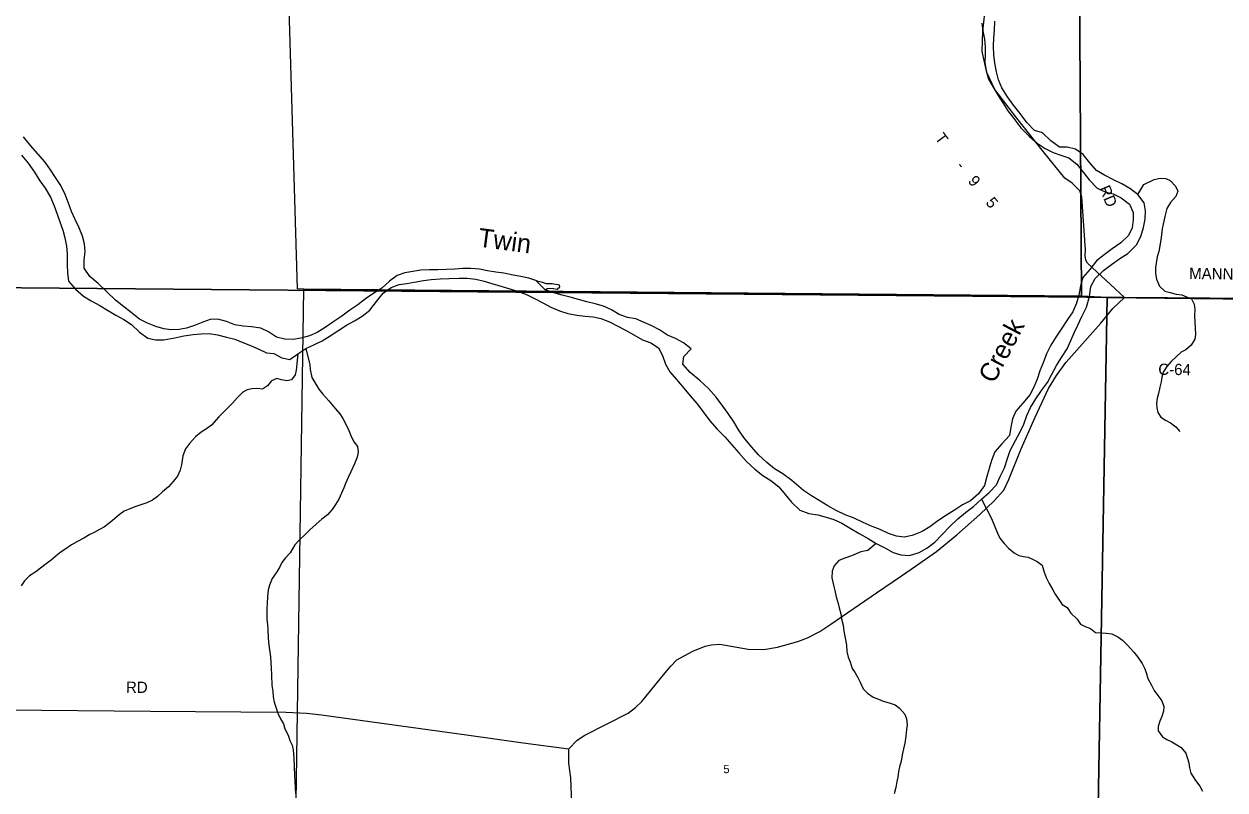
# Model space of a CAD drawing. Extents: x 1312308 to 1684953, y 460642 to 865172.
# Drawn here: x 1414861 to 1422870, y 606234 to 611344 of the extents above; entities that cross this region are included whole.
import ezdxf

# ---------------------------------------------------------------- set-up
doc = ezdxf.new("R2010")
doc.units = 0
for name, color, linetype in [('GM_X_County_Road', 7, 'Continuous'), ('GM_X_County_Road_Text', 7, 'Continuous'), ('GM_X_Major_River', 7, 'Continuous'), ('GM_X_Major_River_Text', 7, 'Continuous'), ('GM_X_Minor_River', 7, 'Continuous'), ('GM_X_Section', 7, 'Continuous'), ('GM_X_Section_Text', 7, 'Continuous'), ('GM_X_Township', 7, 'Continuous'), ('GM_X_Township_Road', 7, 'Continuous'), ('GM_X_Township_Road_Text', 7, 'Continuous')]:
    doc.layers.add(name, color=color, linetype=linetype)

msp = doc.modelspace()

# ---------------------------------------------------------------- linework, layer by layer
at = {"layer": 'GM_X_County_Road'}
for points in [[(1418515, 606139.3), (1418507.2, 606316), (1418493.2, 606412.8), (1418495.3, 606508.5), (1418549.1, 606565.4), (1418600.3, 606599), (1418745.3, 606672.8), (1418888.8, 606746.9), (1418938, 606783.8), (1418982, 606824.4), (1419125.5, 607002.8), (1419174.7, 607060.6), (1419213.9, 607101.3), (1419321.5, 607160.6), (1419402.3, 607193.1), (1419445.8, 607202.2), (1419501.8, 607207), (1419690.2, 607173), (1419794.4, 607171.6), (1419884.8, 607187.8), (1420020.2, 607225.6), (1420084.7, 607248.6), (1420166.9, 607290.6), (1420241.1, 607340.4), (1420545.6, 607548.9), (1420712.5, 607663.1), (1420806.3, 607726.2), (1420946.4, 607824.3), (1421081.6, 607935.3), (1421235.6, 608070.7), (1421331.4, 608162.1), (1421394.2, 608234.5), (1421428.9, 608304.4), (1421511.5, 608508.7), (1421604.6, 608720.3), (1421693.2, 608912), (1421746.6, 608999.1), (1421811.4, 609088.3), (1422041.9, 609347.1), (1422121.7, 609446.2), (1422200.5, 609520.2)], [(1422200.5, 609520.2), (1424759.1, 609498.2), (1427248.1, 609464.9)]]:
    msp.add_lwpolyline(points, dxfattribs=at)
at = {"layer": 'GM_X_Major_River'}
msp.add_line((1418273.9, 609631.9), (1418336.8, 609570.4), dxfattribs=at)
for points in [[(1420656.3, 607819.1), (1420708.1, 607801.9), (1420766.2, 607798.6), (1420830.8, 607819.3), (1420881.5, 607846.2), (1420934.4, 607887.2), (1420983.6, 607938.2), (1421034.8, 607991.2), (1421088, 608042.1), (1421139, 608085.1), (1421192, 608124), (1421245.2, 608174.9), (1421298.2, 608217.9), (1421345.4, 608268.9), (1421370.6, 608324.5), (1421399.9, 608383.9), (1421419.2, 608445.6), (1421438.3, 608499.3), (1421473.8, 608564.7), (1421501, 608618.2), (1421528.2, 608673.7), (1421547.4, 608731.4), (1421572.6, 608784.9), (1421607.9, 608844.3), (1421647.1, 608899.5), (1421686.3, 608952.8), (1421713.5, 609004.3), (1421746.8, 609065.7), (1421780, 609119), (1421817.3, 609176.3), (1421842.5, 609231.9), (1421863.6, 609283.5), (1421888.7, 609335.1), (1421916, 609392.6), (1421945.3, 609454.1), (1421966.9, 609525.8), (1421976.2, 609591.7), (1422003.4, 609645.2), (1422058.7, 609700.1), (1422113.6, 609739), (1422168.6, 609779.8), (1422221.4, 609812.8), (1422278.8, 609869.6), (1422308, 609927.1), (1422327.3, 609986.8), (1422336.5, 610042.7), (1422339.6, 610096.8), (1422330.7, 610151), (1422287.7, 610206.1), (1422234.4, 610245.3), (1422180.9, 610276.5), (1422125.3, 610303.8), (1422065.8, 610335.2), (1422012.3, 610366.4), (1421969.3, 610417.4), (1421924.3, 610472.5), (1421873, 610509.7), (1421817.1, 610522.9), (1421766.9, 610522), (1421707.7, 610563.4), (1421652.6, 610616.7), (1421598.8, 610633.9), (1421547.8, 610687.1), (1421502.9, 610746.2), (1421460, 610803.2), (1421419, 610858.2), (1421382.1, 610917.1), (1421359.2, 610971.7), (1421346.3, 611024.1), (1421335.5, 611084.5), (1421328.5, 611134.7), (1421325.7, 611194.9), (1421328.9, 611250.9), (1421332, 611301), (1421335.2, 611363)], [(1421248.7, 611348.9), (1421255.7, 611298.6), (1421266.6, 611242.3), (1421271.5, 611188.1), (1421270.4, 611138), (1421267.4, 611085.9), (1421276.2, 611031.7), (1421293.1, 610975.2), (1421324.1, 610922.4), (1421357.1, 610867.6), (1421388.1, 610816.8), (1421421.1, 610764), (1421462.1, 610713), (1421509, 610651.8), (1421563.9, 610594.5), (1421617.1, 610549.3), (1421670.5, 610512.1), (1421724.1, 610486.9), (1421775.9, 610469.7), (1421827.6, 610450.5), (1421880.9, 610409.3)], [(1415356.3, 609612.8), (1415301.1, 609660), (1415262.2, 609715), (1415263.3, 609771), (1415268.4, 609823), (1415263.5, 609877.2), (1415250.5, 609927.6), (1415229.6, 609984.1), (1415202.7, 610038.8), (1415177.8, 610093.5), (1415155, 610154.1), (1415136, 610206.6), (1415107.2, 610267.3), (1415072.2, 610320.1), (1415037.2, 610371), (1415002.1, 610421.8), (1414953.1, 610477), (1414904.2, 610534.2), (1414857.3, 610591.3)], [(1414844.7, 610469.3), (1414889.7, 610414.2), (1414930.6, 610355.3), (1414967.5, 610298.4), (1415002.5, 610247.5), (1415037.4, 610188.7), (1415062.2, 610130), (1415083.2, 610075.5), (1415100.1, 610023), (1415119, 609968.5), (1415134, 609918.1), (1415144.9, 609861.8), (1415149.8, 609809.5), (1415148.3, 609737.5), (1415151.2, 609683.3), (1415158.1, 609629), (1415205.1, 609573.9), (1415258.3, 609528.7)], [(1421880.9, 610409.3), (1421923.9, 610356.3), (1421964.9, 610303.3), (1422017.9, 610248), (1422071.6, 610224.8), (1422123.4, 610209.7), (1422177, 610184.4), (1422232.2, 610141.2), (1422257.2, 610086.5), (1422258.1, 610036.4), (1422251.1, 609984.5), (1422225.9, 609932.9), (1422174.8, 609883.9), (1422117.8, 609843.1), (1422064.9, 609804.2), (1422013.9, 609763.2), (1421968.6, 609706.1), (1421921.4, 609653), (1421906.2, 609597.2), (1421894.9, 609535.3), (1421879.7, 609481.6), (1421854.5, 609424), (1421819.3, 609372.7), (1421782.1, 609315.4), (1421742.7, 609254.1), (1421707.5, 609200.8), (1421680.3, 609143.3), (1421657, 609083.7), (1421635.8, 609030), (1421616.6, 608974.3), (1421595.4, 608920.7), (1421568.3, 608869.2), (1421521.1, 608814.1), (1421475.9, 608761), (1421452.7, 608709.4), (1421441.5, 608653.5), (1421432.4, 608597.6), (1421381.1, 608542.6), (1421333.9, 608489.6), (1421312.6, 608431.9), (1421297.5, 608378.2), (1421282.3, 608324.4), (1421267.1, 608264.6), (1421225.8, 608209.4), (1421172.7, 608162.5), (1421120, 608135.6), (1421065.2, 608100.7), (1421012.4, 608067.8), (1420955.4, 608029), (1420902.5, 607990), (1420849.7, 607959.1), (1420783, 607930.5), (1420730.6, 607919.6), (1420678.6, 607926.8), (1420624.8, 607944), (1420569.3, 607971.2), (1420517.6, 607992.4), (1420458, 608017.7), (1420396.4, 608047.1), (1420336.7, 608070.4), (1420277.2, 608097.8), (1420221.7, 608129), (1420164.3, 608164.3), (1420112.8, 608195.5), (1420059.4, 608230.8), (1419980.6, 608298.6), (1419921.4, 608343.9), (1419865.9, 608377.2), (1419814.6, 608418.4), (1419759.5, 608469.7), (1419714.5, 608520.7), (1419667.5, 608575.8), (1419630.6, 608630.8), (1419593.7, 608689.7), (1419556.7, 608744.6), (1419521.7, 608795.4), (1419476.8, 608854.5), (1419425.8, 608911.7), (1419368.8, 608965), (1419303.7, 609018.5), (1419254.8, 609073.7), (1419261.9, 609125.6), (1419311, 609176.7), (1419259.8, 609217.8), (1419206.2, 609245), (1419152.5, 609268.2), (1419099.1, 609303.5), (1419047.6, 609330.6), (1418995.9, 609351.8), (1418940.3, 609377), (1418886.3, 609386.2), (1418830.6, 609405.4), (1418779.1, 609436.6), (1418725.5, 609461.8), (1418669.6, 609477.1), (1418613.8, 609490.3), (1418558, 609505.5), (1418504.1, 609520.7), (1418450.3, 609533.9), (1418394.5, 609551.1), (1418336.8, 609570.4)], [(1418273.9, 609631.9), (1418228.1, 609648.9), (1418174.2, 609660.1), (1418122.3, 609669.2), (1418060.3, 609680.6), (1418008.4, 609687.7), (1417952.4, 609696.9), (1417898.5, 609708.1), (1417840.5, 609713.4), (1417788.3, 609712.5), (1417734.1, 609707.7), (1417677.9, 609704.9), (1417619.7, 609704.1), (1417563.6, 609703.3), (1417507.4, 609700.5), (1417453.1, 609693.7), (1417400.8, 609684.8), (1417350.3, 609665.9), (1417299.4, 609628.9), (1417246.3, 609582), (1417193.4, 609547), (1417138.5, 609510.2), (1417087.6, 609469.2), (1417034.7, 609434.2), (1416979.8, 609395.4), (1416920.8, 609354.6), (1416869.9, 609319.6), (1416817.1, 609286.7), (1416764.5, 609263.8), (1416708, 609247), (1416655.8, 609240.1), (1416599.7, 609241.3), (1416545.8, 609254.5), (1416492.4, 609289.7), (1416440.8, 609314.8), (1416378.8, 609324.2), (1416322.8, 609327.4), (1416266.8, 609336.6), (1416211.2, 609359.9), (1416153.3, 609375.2), (1416103.1, 609372.2), (1416052.7, 609355.3), (1415998.1, 609332.4), (1415945.6, 609315.5), (1415895.3, 609306.6), (1415845.1, 609303.7), (1415793.1, 609310.8), (1415739.3, 609326), (1415683.6, 609347.2), (1415632, 609374.4), (1415574.8, 609419.7), (1415523.5, 609458.9), (1415472.3, 609502), (1415413.3, 609557.4), (1415356.3, 609612.8)], [(1415258.3, 609528.7), (1415309.8, 609497.5), (1415367.3, 609466.2), (1415418.8, 609435.1), (1415474.2, 609401.8), (1415525.7, 609372.7), (1415577.2, 609339.5), (1415630.2, 609288.3), (1415687.6, 609249), (1415739.4, 609235.8), (1415793.6, 609236.7), (1415866.1, 609251.1), (1415926.5, 609263.8), (1415988.8, 609272.5), (1416043, 609277.4), (1416095.2, 609278.2), (1416151.2, 609271), (1416211, 609255.7), (1416266.8, 609240.5), (1416320.5, 609219.3), (1416372.2, 609198.1), (1416425.9, 609174.9), (1416477.5, 609149.8), (1416527.5, 609146.7), (1416581.1, 609117.5), (1416633, 609106.3), (1416687.9, 609143.2), (1416740.7, 609178.1), (1416797.4, 609205), (1416850, 609229.9), (1416902.9, 609262.8), (1416953.7, 609297.8), (1417012.6, 609334.5), (1417065.3, 609363.5), (1417116.1, 609394.4), (1417167.1, 609435.4), (1417212.4, 609492.5), (1417255.6, 609547.7), (1417310.5, 609586.6), (1417363.1, 609605.5), (1417413.3, 609612.4), (1417463.6, 609621.3), (1417526, 609632), (1417576.3, 609638.9), (1417636.5, 609643.7), (1417696.7, 609646.4), (1417763, 609648.9), (1417817.1, 609647.8), (1417873.1, 609640.5), (1417928.9, 609627.3), (1417980.7, 609612.2), (1418100.3, 609577.5), (1418158.1, 609558.2), (1418215.8, 609537), (1418269.3, 609509.8), (1418320.9, 609482.6), (1418374.5, 609455.4), (1418432.1, 609430.1), (1418487.9, 609412.9), (1418547.8, 609401.5), (1418603.8, 609394.3), (1418655.8, 609389.2), (1418707.7, 609378.1), (1418765.4, 609356.8), (1418872.5, 609302.3), (1418928, 609269.1), (1418985.5, 609237.8), (1419041.2, 609216.5), (1419092.6, 609183.4), (1419119.7, 609132.7), (1419138.5, 609074.2), (1419167.5, 609023.5), (1419212.6, 608972.4), (1419261.5, 608915.2), (1419302.6, 608864.3), (1419347.6, 608811.2), (1419390.5, 608756.2), (1419433.4, 608697.1), (1419482.4, 608640), (1419533.5, 608590.8), (1419580.5, 608535.7), (1419627.5, 608482.5), (1419678.4, 608425.3), (1419733.5, 608374.1), (1419788.8, 608332.8), (1419842.2, 608297.6), (1419893.5, 608256.4), (1419936.5, 608205.4), (1419979.6, 608154.3), (1420034.6, 608101), (1420094.3, 608077.7), (1420154.2, 608068.4), (1420210.1, 608053.2), (1420261.9, 608038), (1420315.5, 608012.8), (1420370.9, 607979.5), (1420430.4, 607944.2), (1420489.8, 607910.8), (1420543.3, 607877.6), (1420604.8, 607846.2), (1420656.3, 607819.1)], [(1418336.8, 609570.4), (1418349, 609580.2), (1418363.1, 609581.9), (1418391.1, 609579.3), (1418417, 609574.7), (1418433.4, 609590.4), (1418431.6, 609600.4), (1418423.6, 609602.6), (1418405.7, 609607), (1418383.7, 609609.5), (1418345.6, 609610.3), (1418319.7, 609618.9), (1418289.8, 609625.5), (1418273.9, 609631.9)]]:
    msp.add_lwpolyline(points, dxfattribs=at)
at = {"layer": 'GM_X_Minor_River'}
for points in [[(1422287.7, 610206.1), (1422327.8, 610273.7), (1422396.6, 610306.5), (1422436.9, 610315.8), (1422475, 610313.1), (1422504.8, 610300.5), (1422540.1, 610261.7), (1422555.5, 610229.3), (1422542.8, 610193.4), (1422505.8, 610154), (1422482.9, 610112.3), (1422467.8, 610058.4), (1422456.7, 610008.4), (1422450, 609976.4), (1422447.3, 609938.3), (1422442.6, 609904.3), (1422428.9, 609826.3), (1422418.2, 609790.4), (1422411.3, 609748.4), (1422406.6, 609718.4), (1422405.8, 609678.3), (1422413.1, 609642), (1422432.2, 609595.5), (1422469.6, 609560.7), (1422503.5, 609552.1), (1422543.4, 609541.3), (1422581.4, 609536.6), (1422613.3, 609523.9), (1422647.1, 609509.3), (1422664.4, 609474.8), (1422667.7, 609438.7), (1422666.9, 609398.5), (1422668, 609356.4), (1422671.2, 609314.2), (1422672.3, 609272), (1422669.7, 609242), (1422644.8, 609200.3), (1422608.1, 609170.9), (1422577.6, 609155.4), (1422547, 609125.9), (1422510.2, 609092.5), (1422481.4, 609058.9), (1422458.5, 609021.2), (1422447.8, 608987.3), (1422443.2, 608957.3), (1422434.4, 608921.3), (1422425.6, 608879.3), (1422416.9, 608847.4), (1422412.2, 608813.4), (1422415.6, 608783.2), (1422422.9, 608751), (1422442.4, 608720.5), (1422472, 608699.9), (1422505.8, 608683.2), (1422541.3, 608656.5), (1422568.8, 608625.9)], [(1416687.9, 609143.2), (1416675.9, 609033.9), (1416669.3, 609003.9), (1416644.5, 608970.3), (1416614.3, 608962.8), (1416578.3, 608969.5), (1416546.4, 608978.1), (1416512, 608962.7), (1416485.2, 608929.1), (1416450.7, 608907.7), (1416418.7, 608912.3), (1416380.5, 608911), (1416350.3, 608903.5), (1416319.9, 608888), (1416285.1, 608852.5), (1416252.2, 608815), (1416221.5, 608785.5), (1416160, 608722.4), (1416110.8, 608667.2), (1416078.2, 608643.7), (1416041.6, 608620.3), (1416004.9, 608588.9), (1415963.9, 608545.5), (1415937.1, 608509.9), (1415920, 608462), (1415910.8, 608402), (1415902.1, 608368.1), (1415885.2, 608328.3), (1415856.4, 608292.7), (1415825.6, 608257.2), (1415784.7, 608221.8), (1415752, 608192.3), (1415717.4, 608166.9), (1415680.9, 608149.5), (1415600.2, 608122.9), (1415561.8, 608107.5), (1415529.4, 608094.1), (1415494.8, 608068.7), (1415464.2, 608043.1), (1415427.4, 608011.7), (1415396.9, 607990.2), (1415364.4, 607970.8), (1415329.9, 607951.3), (1415299.5, 607937.8), (1415260.9, 607914.5), (1415214.3, 607889.3), (1415177.8, 607869.9), (1415141.1, 607842.5), (1415108.6, 607823), (1415076, 607795.5), (1415041.3, 607768.1), (1415008.7, 607742.6), (1414972, 607713.2), (1414939.4, 607689.7), (1414898.7, 607662.4), (1414863.9, 607628.9), (1414841.2, 607595.2)], [(1416740.7, 609178.1), (1416766.9, 609070.4), (1416770.3, 609038.2), (1416781.2, 608985.8), (1416800.6, 608951.4), (1416827.7, 608906.7), (1416853.2, 608874.2), (1416894.4, 608829.3), (1416937.4, 608776.3), (1416966.8, 608743.7), (1416988.2, 608711.2), (1417007.5, 608674.7), (1417026.7, 608632.2), (1417045.9, 608587.7), (1417063.2, 608555.3), (1417084.7, 608524.8), (1417089.9, 608486.6), (1417083.2, 608454.6), (1417064.3, 608408.8), (1417041.1, 608357.1), (1417022.3, 608319.3), (1417005.4, 608279.5), (1416994.8, 608249.6), (1416961.2, 608174), (1416938.4, 608138.3), (1416915.6, 608104.6), (1416884.8, 608069.1), (1416848.1, 608039.7), (1416809.3, 608008.3), (1416766.4, 607969), (1416735.7, 607937.4), (1416698.8, 607902), (1416666.1, 607868.5), (1416634.9, 607816.9), (1416604.1, 607783.4), (1416579.4, 607751.7), (1416564.7, 607717.9), (1416541.9, 607682.2), (1416515, 607644.6), (1416498.1, 607600.8), (1416489.4, 607568.8), (1416484.5, 607522.8), (1416481.6, 607478.7), (1416480.9, 607446.6), (1416480.2, 607414.5), (1416481.4, 607372.4), (1416484.7, 607336.2), (1416486, 607304.1), (1416488.9, 607249.9), (1416493.9, 607199.6), (1416497.3, 607169.5), (1416504.3, 607121.2), (1416508.8, 607046.9), (1416511.9, 607002.7), (1416514.5, 606930.4), (1416519.7, 606892.2), (1416523, 606856), (1416530.2, 606819.8), (1416539.6, 606787.5), (1416552.8, 606747.2), (1416572.1, 606708.7), (1416591.5, 606676.2), (1416600.8, 606642), (1416622, 606599.4), (1416633.3, 606565.1), (1416648.7, 606532.8), (1416656.1, 606502.5), (1416660.9, 606444.2), (1416661.9, 606392.1), (1416664.6, 606327.8), (1416667.9, 606293.7), (1416668.9, 606247.5), (1416672.2, 606211.3)], [(1421245.2, 608174.9), (1421313.2, 608045.3), (1421336.1, 607984.7), (1421353.3, 607946.3), (1421368.7, 607913.9), (1421398.1, 607877.2), (1421425.5, 607846.6), (1421463, 607815.8), (1421494.7, 607797.2), (1421526.7, 607790.6), (1421556.7, 607786), (1421586.5, 607773.4), (1421618.3, 607758.8), (1421649.9, 607734.1), (1421663, 607687.7), (1421678.3, 607651.3), (1421697.5, 607610.9), (1421722.7, 607570.2), (1421738.2, 607539.9), (1421784.9, 607470.8), (1421816.6, 607452.2), (1421841.9, 607413.6), (1421883.2, 607372.7), (1421906.6, 607340.1), (1421936.4, 607325.5), (1421972.2, 607310.8), (1422005.7, 607284.1), (1422043.8, 607281.4), (1422077.9, 607280.8), (1422115.9, 607276), (1422155.6, 607255.2), (1422185.2, 607232.6), (1422220.6, 607199.8), (1422261.8, 607152.9), (1422289.2, 607120.3), (1422316.4, 607077.7), (1422333.9, 607047.3), (1422343.3, 607017), (1422354.5, 606978.7), (1422379.7, 606934.1), (1422397, 606897.6), (1422422.4, 606865.1), (1422447.7, 606828.5), (1422461, 606790.1), (1422460.4, 606760), (1422449.6, 606724.1), (1422434.9, 606692.3), (1422424.2, 606658.4), (1422423.6, 606628.3), (1422452.9, 606589.6), (1422482.6, 606571), (1422514.3, 606554.4), (1422548, 606535.7), (1422577.7, 606517.1), (1422609.1, 606480.4), (1422627.8, 606415.8), (1422633.1, 606381.6), (1422642.5, 606347.3), (1422673.5, 606296.6), (1422700.9, 606260), (1422720.2, 606225.5)], [(1420543.3, 607877.6), (1420488.5, 607831.9), (1420442.1, 607822.8), (1420409.8, 607809.3), (1420379.4, 607795.8), (1420335, 607780.6), (1420294.5, 607765.3), (1420263.7, 607729.8), (1420250.9, 607693.9), (1420248, 607649.8), (1420259, 607599.5), (1420268.4, 607565.2), (1420277.5, 607522.9), (1420290.7, 607478.5), (1420296.1, 607448.3), (1420307.3, 607410), (1420312.6, 607375.8), (1420323.8, 607333.4), (1420329, 607293.2), (1420334.3, 607261), (1420345.1, 607200.6), (1420348.3, 607158.4), (1420357.5, 607120.2), (1420370.9, 607087.8), (1420384.1, 607045.4), (1420403.5, 607015), (1420421, 606984.6), (1420436.3, 606952.2), (1420457.5, 606909.7), (1420485, 606879), (1420524.6, 606852.2), (1420558.4, 606839.6), (1420590.2, 606826.9), (1420630.1, 606816.2), (1420669.9, 606801.4), (1420699.6, 606780.8), (1420734.9, 606740), (1420746.2, 606707.7), (1420749.5, 606669.5), (1420746.8, 606637.4), (1420741.9, 606593.4), (1420734.9, 606547.4), (1420726.1, 606509.4), (1420717.3, 606467.5), (1420710.4, 606425.5), (1420699.6, 606387.6), (1420692.9, 606357.6), (1420688.2, 606319.6), (1420681.5, 606289.6), (1420674.7, 606249.6), (1420663.8, 606207.7)]]:
    msp.add_lwpolyline(points, dxfattribs=at)
at = {"layer": 'GM_X_Section'}
for points in [[(1421880.4, 614765), (1421912, 609528.3), (1416727.1, 609575.6), (1416685.1, 609576.5), (1416536.6, 614585.6)], [(1427084.1, 614755.3), (1427288.4, 609459), (1422083.8, 609518.6), (1421912, 609528.3), (1421880.4, 614765)], [(1416727.1, 609575.6), (1421912, 609528.3), (1422083.8, 609518.6), (1421984.3, 603858.8), (1416641.9, 603929.4)], [(1422083.8, 609518.6), (1427288.4, 609459), (1427408.4, 609456.4), (1427318.8, 603698.4), (1421984.3, 603858.8)]]:
    msp.add_lwpolyline(points, close=True, dxfattribs=at)
at = {"layer": 'GM_X_Township'}
for points in [[(1443487.4, 629689.1), (1443383.2, 625252.4), (1443279.1, 619936.6), (1443262.6, 619245.4), (1443164.3, 614625), (1443062.5, 609310), (1440472, 609335.1), (1437771.4, 609361.5), (1435199.7, 609380.4), (1434197.2, 609392.5), (1430057.8, 609437.8), (1427248.1, 609464.9), (1424759.1, 609498.2), (1422200.5, 609520.2), (1411036.3, 609617.7), (1410999.4, 609618.2), (1411017.8, 611981.1), (1411020.1, 612268.6), (1411090.2, 617032.9), (1411094.7, 617623.7), (1411153.4, 624951), (1411163.3, 625647.7), (1411180.4, 628296.4), (1411210.5, 633565.2)], [(1410955.4, 603991.6), (1410977, 606750.9), (1410982, 607392.1), (1410997.9, 609428.6), (1410999.4, 609618.2), (1411036.3, 609617.7), (1422200.5, 609520.2), (1424759.1, 609498.2), (1427248.1, 609464.9), (1430057.8, 609437.8), (1434197.2, 609392.5), (1435199.7, 609380.4), (1437771.4, 609361.5), (1440472, 609335.1), (1443062.5, 609310), (1445748.3, 609283.3), (1452218.2, 609194.8), (1453828.1, 609169), (1453803.6, 608986.7), (1453761.5, 603813.9)]]:
    msp.add_lwpolyline(points, dxfattribs=at)
at = {"layer": 'GM_X_Township_Road'}
for points in [[(1422200.5, 609520.2), (1421953.8, 609748.1), (1421941.9, 609768.1), (1421938.2, 609800), (1421939.4, 609837), (1421914.4, 610191.3), (1421901.9, 610231.4), (1421850.6, 610282.7), (1421801.7, 610316.1), (1421660.2, 610490.5), (1421481.2, 610714.6), (1421336, 610906.2), (1421280.9, 611020.1), (1421250.8, 611159.1), (1421255.9, 611295.6), (1421278.4, 611517.2)], [(1410994, 607386.4), (1412476.3, 607367.6), (1412503.2, 607351.1), (1412514.9, 607332.1), (1412520.4, 607305.2), (1412505.7, 606849.6), (1412515.5, 606820.2), (1412544.8, 606797), (1413589, 606785.5), (1414490, 606771.8), (1415704.5, 606760.5), (1416606.9, 606752.9), (1416745.7, 606747.2), (1416844.8, 606734.6), (1417826.8, 606599.6), (1418189.9, 606549.3), (1418495.3, 606508.5)]]:
    msp.add_lwpolyline(points, dxfattribs=at)

# ---------------------------------------------------------------- texts
at = {"layer": 'GM_X_County_Road_Text'}
for s, rotation, p in [('MANNING', 359.28902, (1422630.5, 609642.5)), ('C-64', 359.31292, (1422424.7, 609003.3))]:
    msp.add_text(s, height=75, rotation=rotation, dxfattribs=at).set_placement(p)
at = {"layer": 'GM_X_Major_River_Text'}
for s, height, rotation, p in [('Twin', 125, 352.42086, (1417884, 609859.4)), ('Creek', 124.98, 62.35598, (1421329.6, 608938.9))]:
    msp.add_text(s, height=height, rotation=rotation, dxfattribs=at).set_placement(p)
at = {"layer": 'GM_X_Section_Text'}
msp.add_text('5', height=55.3, rotation=0.00001, dxfattribs=at).set_placement((1419524.8, 606346.3))
at = {"layer": 'GM_X_Township_Road_Text'}
for s, rotation, p in [('T', 306.72419, (1420932.1, 610582)), ('-', 308.52304, (1421072.5, 610394)), ('9', 309.24191, (1421151.8, 610294.4)), ('RD', 292.80932, (1422029.3, 610247.8)), ('5', 309.52865, (1421269.8, 610150)), ('RD', 359.50892, (1415540.7, 606882.5))]:
    msp.add_text(s, height=75, rotation=rotation, dxfattribs=at).set_placement(p)

doc.saveas('drawing.dxf')
